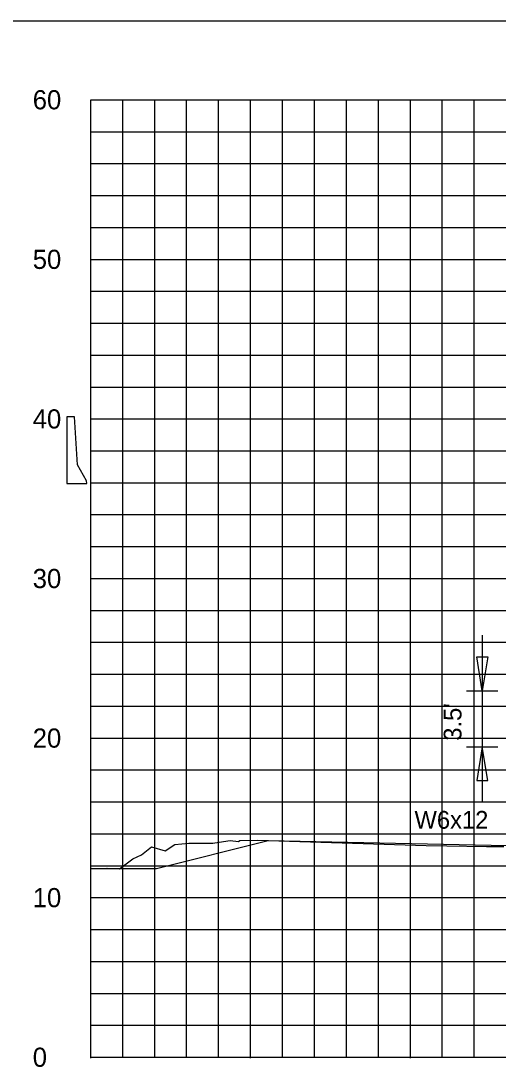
# Model space of a CAD drawing. Extents: x 1797809 to 2198143, y 249608 to 1237864.
# Drawn here: x 2195038.5 to 2195068.4, y 1237162.5 to 1237228 of the extents above; entities that cross this region are included whole.
import ezdxf

# ---------------------------------------------------------------- set-up
doc = ezdxf.new("R2010")
doc.units = 0
for name, color, linetype in [('3', 7, 'Continuous'), ('31', 7, 'Continuous'), ('60', 7, 'Continuous'), ('DESIGN - SHEET - Light Grid', 7, 'Continuous'), ('DESIGN - TRAFFIC CONTROL PERMANENT - Signs', 7, 'Continuous'), ('GSBWFILL', 7, 'Continuous'), ('GSDIMS', 7, 'Continuous'), ('GSSHT', 7, 'Continuous'), ('Level 55', 7, 'Continuous')]:
    doc.layers.add(name, color=color, linetype=linetype)

msp = doc.modelspace()

# ---------------------------------------------------------------- linework, layer by layer
at = {"layer": '3'}
msp.add_line((2194882.86, 1237228.046), (2195182.86, 1237228.046), dxfattribs=at)
at = {"layer": '60'}
for p, q in [((2195042.86, 1237163.106), (2195042.86, 1237223.106)), ((2195042.86, 1237163.046), (2195042.86, 1237163.106)), ((2195042.86, 1237163.106), (2195172.86, 1237163.106)), ((2195052.86, 1237163.046), (2195052.86, 1237163.106)), ((2195062.86, 1237163.046), (2195062.86, 1237163.106))]:
    msp.add_line(p, q, dxfattribs=at)
at = {"layer": 'DESIGN - SHEET - Light Grid'}
msp.add_lwpolyline([(2195042.86, 1237174.931), (2195043.855, 1237174.952), (2195043.891, 1237174.938), (2195044.661, 1237174.902), (2195045.493, 1237175.534), (2195046.037, 1237175.782), (2195046.66, 1237176.284), (2195047.523, 1237176.048), (2195048.126, 1237176.436), (2195048.993, 1237176.526), (2195050.5, 1237176.526), (2195051.17, 1237176.632), (2195051.581, 1237176.696), (2195052.096, 1237176.635), (2195052.198, 1237176.696), (2195053.323, 1237176.702), (2195063.854, 1237176.368), (2195065.145, 1237176.363), (2195067.627, 1237176.306), (2195068.719, 1237176.306)], dxfattribs=at)
at = {"layer": 'DESIGN - TRAFFIC CONTROL PERMANENT - Signs'}
msp.add_line((2195042.86, 1237174.933), (2195045.966, 1237174.933), dxfattribs=at)
msp.add_lwpolyline([(2195042.966, 1237174.933), (2195046.966, 1237174.933), (2195053.962, 1237176.682), (2195086.873, 1237175.99), (2195090.873, 1237175.83), (2195091.203, 1237175.83), (2195091.37, 1237175.33), (2195093.37, 1237175.49), (2195096.86, 1237175.566), (2195112.86, 1237175.918), (2195120.86, 1237175.974), (2195122.86, 1237175.987), (2195123.358, 1237176.07)], dxfattribs=at)
at = {"layer": 'GSBWFILL'}
msp.add_lwpolyline([(2195041.836, 1237203.233), (2195041.356, 1237203.233), (2195041.356, 1237199.053), (2195042.586, 1237199.053), (2195042.606, 1237199.053), (2195042.586, 1237199.223), (2195042.036, 1237200.223), (2195041.836, 1237203.233)], dxfattribs=at)
at = {"layer": 'GSDIMS'}
for p, q in [((2195067.361, 1237189.563), (2195067.361, 1237179.066)), ((2195066.377, 1237186.063), (2195068.345, 1237186.063)), ((2195066.377, 1237182.566), (2195068.345, 1237182.566))]:
    msp.add_line(p, q, dxfattribs=at)
for points in [[(2195067.361, 1237186.063), (2195067.014, 1237188.191), (2195067.708, 1237188.191)], [(2195067.361, 1237182.566), (2195067.014, 1237180.438), (2195067.708, 1237180.438)]]:
    msp.add_lwpolyline(points, close=True, dxfattribs=at)
at = {"layer": 'GSSHT'}
for p, q in [((2195042.86, 1237223.106), (2195172.86, 1237223.106)), ((2195044.86, 1237163.106), (2195044.86, 1237223.106)), ((2195046.86, 1237163.106), (2195046.86, 1237223.106)), ((2195048.86, 1237163.106), (2195048.86, 1237223.106)), ((2195050.86, 1237163.106), (2195050.86, 1237223.106)), ((2195052.86, 1237163.106), (2195052.86, 1237223.106)), ((2195054.86, 1237163.106), (2195054.86, 1237223.106)), ((2195056.86, 1237163.106), (2195056.86, 1237223.106)), ((2195058.86, 1237163.106), (2195058.86, 1237223.106)), ((2195060.86, 1237163.106), (2195060.86, 1237223.106)), ((2195062.86, 1237163.106), (2195062.86, 1237223.106)), ((2195064.86, 1237163.106), (2195064.86, 1237223.106)), ((2195066.86, 1237163.106), (2195066.86, 1237223.106)), ((2195042.86, 1237221.106), (2195172.86, 1237221.106)), ((2195042.86, 1237219.106), (2195172.86, 1237219.106)), ((2195042.86, 1237217.106), (2195172.86, 1237217.106)), ((2195042.86, 1237215.106), (2195172.86, 1237215.106)), ((2195042.86, 1237213.106), (2195172.86, 1237213.106)), ((2195042.86, 1237211.106), (2195172.86, 1237211.106)), ((2195042.86, 1237209.106), (2195172.86, 1237209.106)), ((2195042.86, 1237207.106), (2195172.86, 1237207.106)), ((2195042.86, 1237205.106), (2195172.86, 1237205.106)), ((2195042.86, 1237203.106), (2195172.86, 1237203.106)), ((2195042.86, 1237201.106), (2195172.86, 1237201.106)), ((2195042.86, 1237199.106), (2195172.86, 1237199.106)), ((2195042.86, 1237197.106), (2195172.86, 1237197.106)), ((2195042.86, 1237195.106), (2195172.86, 1237195.106)), ((2195042.86, 1237193.106), (2195172.86, 1237193.106)), ((2195042.86, 1237191.106), (2195172.86, 1237191.106)), ((2195042.86, 1237189.106), (2195172.86, 1237189.106)), ((2195042.86, 1237187.106), (2195172.86, 1237187.106)), ((2195042.86, 1237185.106), (2195172.86, 1237185.106)), ((2195042.86, 1237183.106), (2195172.86, 1237183.106)), ((2195042.86, 1237181.106), (2195172.86, 1237181.106)), ((2195042.86, 1237179.106), (2195172.86, 1237179.106)), ((2195042.86, 1237177.106), (2195172.86, 1237177.106)), ((2195042.86, 1237175.106), (2195172.86, 1237175.106)), ((2195042.86, 1237173.106), (2195172.86, 1237173.106)), ((2195042.86, 1237171.106), (2195172.86, 1237171.106)), ((2195042.86, 1237169.106), (2195172.86, 1237169.106)), ((2195042.86, 1237167.106), (2195172.86, 1237167.106)), ((2195042.86, 1237165.106), (2195172.86, 1237165.106)), ((2195042.86, 1237163.106), (2195172.86, 1237163.106))]:
    msp.add_line(p, q, dxfattribs=at)

# ---------------------------------------------------------------- texts
at = {"layer": '31'}
for s, p in [('60', (2195039.226, 1237222.506)), ('50', (2195039.226, 1237212.506)), ('40', (2195039.226, 1237202.506)), ('30', (2195039.226, 1237192.506)), ('20', (2195039.226, 1237182.506)), ('10', (2195039.226, 1237172.506)), ('0', (2195039.226, 1237162.506))]:
    msp.add_text(s, height=1.2, dxfattribs=at).set_placement(p)
at = {"layer": 'Level 55'}
for s, rotation, p in [("3.5'", 90, (2195066.06, 1237182.942)), ('W6x12', 360, (2195063.121, 1237177.428))]:
    msp.add_text(s, height=1.1105, rotation=rotation, dxfattribs=at).set_placement(p)

doc.saveas('drawing.dxf')
